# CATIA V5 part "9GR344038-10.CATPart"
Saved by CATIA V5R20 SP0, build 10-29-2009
Part number: 9GR344038-10
Revision: ANY
Definition: UNKNOWN
Nomenclature: 9GR344038-10
Source: Unknown
Bounding box of the stored display mesh (mm): x -18.905 to 18.807, y -35 to 5, z -19 to 19
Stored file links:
  C:\Users\Utente\Desktop\IO LAVORO\3D X SITO CF\CUMSA\3D files GR\GR 344038-10\9GR344038-10.CATPart
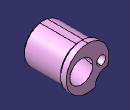
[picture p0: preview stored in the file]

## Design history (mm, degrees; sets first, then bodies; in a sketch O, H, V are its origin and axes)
Body1 "Cortar-Extruir7" (main body)
  Solid1: solid without history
